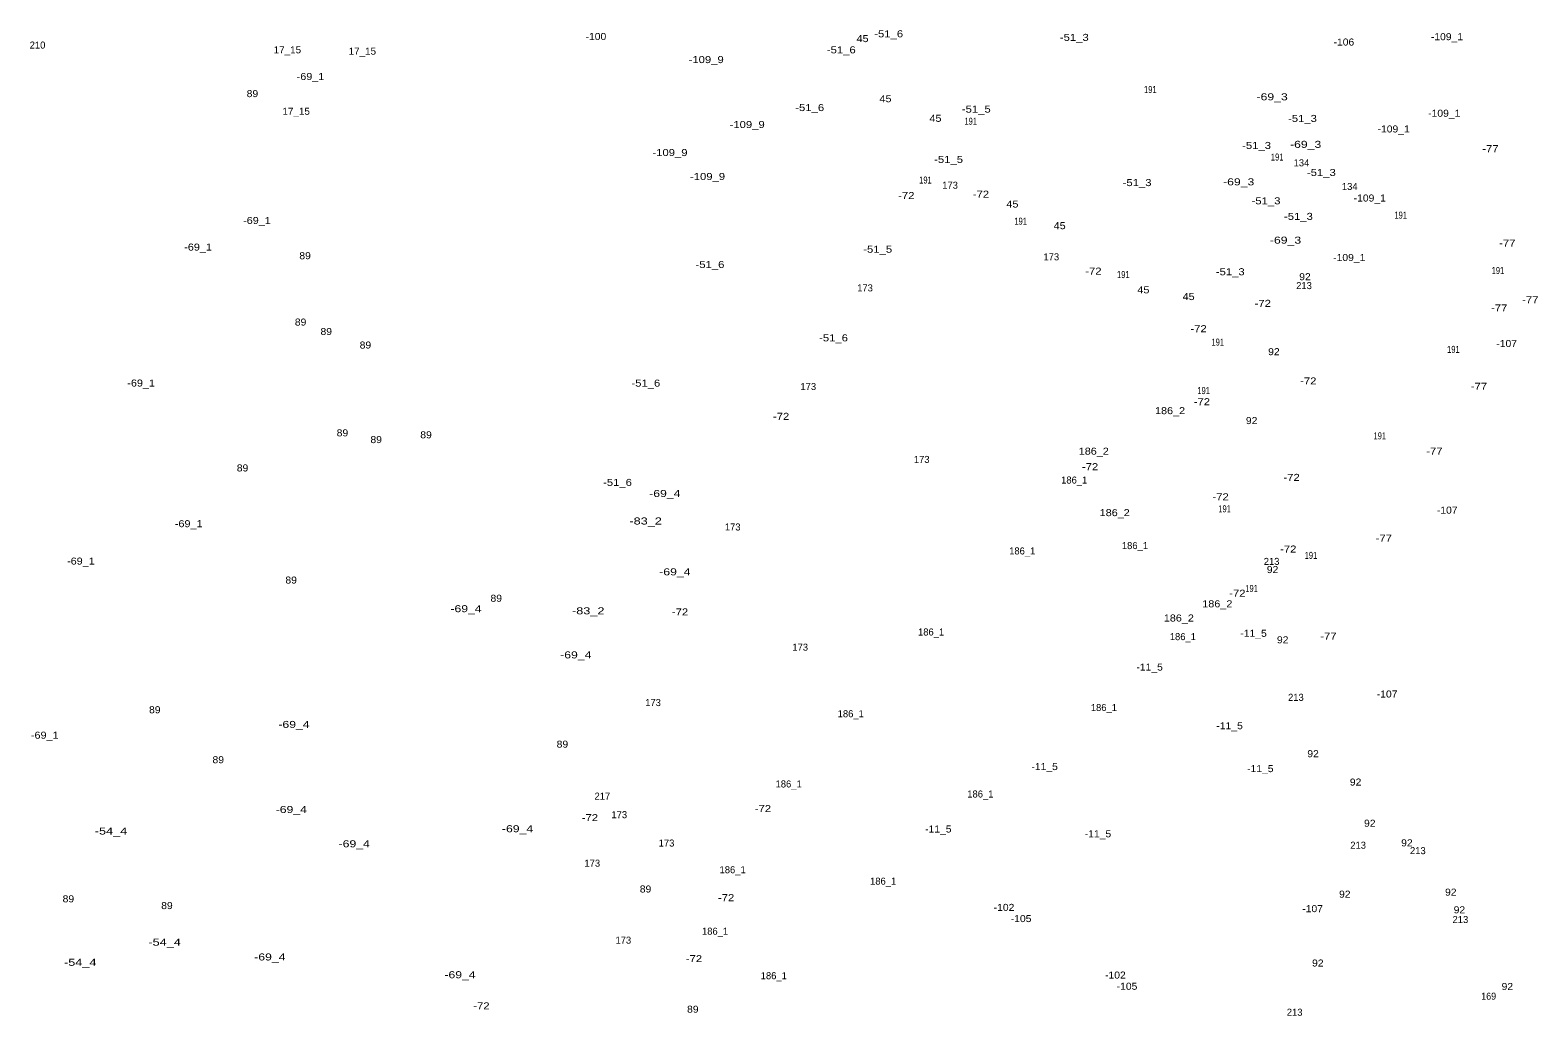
# Model space of a CAD drawing. Extents: x -662996 to -659766, y -998554 to -993949.
# Drawn here: x -660768 to -659910, y -996835 to -996274 of the extents above; entities that cross this region are included whole.
import ezdxf
from ezdxf.enums import TextEntityAlignment as Align

# ---------------------------------------------------------------- set-up
doc = ezdxf.new("R2010")
doc.units = 0
doc.header["$LTSCALE"] = 1.6
doc.layers.add('24', color=7, linetype='Continuous')

msp = doc.modelspace()

# ---------------------------------------------------------------- texts
at = {"layer": '24'}
for s, width, p in [('-100', 1.1, (-660445.981, -996279.57)), ('45', 1.15, (-660294.29, -996280.8)), ('-51_6', 1.2, (-660279.421, -996278.06)), ('-51_3', 1.2, (-660173.84, -996280.11)), ('-109_1', 1.1, (-659961.841, -996279.71)), ('17_15', 1.05, (-660621.48, -996287.18)), ('17_15', 1.05, (-660578.85, -996287.95)), ('-51_6', 1.2, (-660306.39, -996287.19)), ('-106', 1.1, (-660020.48, -996282.75)), ('-109_9', 1.2, (-660383.25, -996292.74)), ('-69_1', 1.15, (-660608.33, -996302.34)), ('89', 1.1, (-660641.37, -996312.09)), ('45', 1.15, (-660281.24, -996314.99)), ('191', 0.8, (-660130.62, -996309.76)), ('-69_3', 1.3, (-660061.29, -996313.9)), ('17_15', 1.05, (-660616.49, -996322.14)), ('-51_6', 1.2, (-660324.351, -996320.03)), ('-51_5', 1.2, (-660229.59, -996320.9)), ('-109_1', 1.1, (-659963.39, -996323.26)), ('-109_9', 1.2, (-660359.93, -996329.68)), ('45', 1.15, (-660252.819, -996326.13)), ('191', 0.8, (-660232.76, -996327.81)), ('-51_3', 1.2, (-660044.04, -996326.21)), ('-109_1', 1.1, (-659992.16, -996332.2)), ('-51_3', 1.2, (-660070.15, -996341.57)), ('-69_3', 1.3, (-660042.25, -996340.95)), ('-109_9', 1.2, (-660403.85, -996345.62)), ('-51_5', 1.2, (-660245.35, -996349.52)), ('191', 0.8, (-660058.421, -996348.17)), ('-77', 1.2, (-659937.12, -996343.41)), ('-51_3', 1.2, (-660033.29, -996356.94)), ('-109_9', 1.2, (-660382.47, -996359.23)), ('191', 0.8, (-660258.49, -996361.24)), ('-51_3', 1.2, (-660138.12, -996362.7)), ('-69_3', 1.3, (-660080.33, -996362.28)), ('-72', 1.2, (-660269.4, -996370.07)), ('-72', 1.2, (-660226.941, -996369.29)), ('45', 1.15, (-660209.04, -996374.91)), ('-51_3', 1.2, (-660064.78, -996373.07)), ('-109_1', 1.1, (-660005.76, -996371.47)), ('-69_1', 1.15, (-660638.79, -996384.24)), ('191', 0.8, (-660204.351, -996384.67)), ('-51_3', 1.2, (-660046.34, -996381.91)), ('191', 0.8, (-659988.15, -996381.21)), ('45', 1.15, (-660182.16, -996387.21)), ('-69_1', 1.15, (-660672.3, -996399.38)), ('-51_5', 1.2, (-660285.669, -996400.61)), ('-69_3', 1.3, (-660053.68, -996395.43)), ('-77', 1.2, (-659927.52, -996397.11)), ('89', 1.1, (-660611.42, -996404.29)), ('-51_6', 1.2, (-660381.091, -996409.3)), ('-109_1', 1.1, (-660017.421, -996405.3)), ('-72', 1.2, (-660162.961, -996413.05)), ('191', 0.8, (-660145.981, -996415.02)), ('-51_3', 1.2, (-660085.13, -996413.41)), ('92', 1.1, (-660042.61, -996416.24)), ('191', 0.8, (-659932.851, -996412.71)), ('45', 1.15, (-660134.54, -996423.7)), ('45', 1.15, (-660108.809, -996427.54)), ('-72', 1.2, (-660066.611, -996431.39)), ('-77', 1.2, (-659932.13, -996433.99)), ('-77', 1.2, (-659914.459, -996429.38)), ('89', 1.1, (-660613.96, -996442.03)), ('89', 1.1, (-660599.37, -996447.41)), ('-51_6', 1.2, (-660310.811, -996451.02)), ('-72', 1.2, (-660103.171, -996445.81)), ('191', 0.8, (-660092.211, -996453.43)), ('89', 1.1, (-660577.1, -996455.1)), ('92', 1.1, (-660060.28, -996458.88)), ('191', 0.8, (-659958.191, -996457.57)), ('-107', 1.1, (-659927.88, -996454.22)), ('-69_1', 1.15, (-660704.67, -996476.71)), ('-51_6', 1.2, (-660417.571, -996476.76)), ('-72', 1.2, (-660040.721, -996475.52)), ('-77', 1.2, (-659943.65, -996478.55)), ('-72', 1.2, (-660101.27, -996487.34)), ('191', 0.8, (-660100.28, -996481.01)), ('-72', 1.2, (-660340.62, -996495.66)), ('186_2', 1.15, (-660119.36, -996492.42)), ('92', 1.1, (-660072.95, -996498.07)), ('89', 1.1, (-660590.16, -996505.04)), ('89', 1.1, (-660570.96, -996508.88)), ('89', 1.1, (-660542.61, -996506.17)), ('191', 0.8, (-660000.051, -996506.74)), ('186_2', 1.15, (-660162.76, -996515.47)), ('-77', 1.2, (-659968.99, -996515.43)), ('89', 1.1, (-660646.99, -996525.01)), ('-72', 1.2, (-660164.861, -996524.29)), ('-72', 1.2, (-660050.24, -996530.38)), ('-51_6', 1.2, (-660433.701, -996533.23)), ('-69_4', 1.3, (-660406.77, -996539.54)), ('-72', 1.2, (-660090.611, -996541.43)), ('-83_2', 1.35, (-660417.699, -996555.18)), ('186_2', 1.15, (-660150.85, -996550.43)), ('191', 0.8, (-660088.37, -996548.23)), ('-107', 1.1, (-659961.7, -996548.99)), ('-69_1', 1.15, (-660677.63, -996556.71)), ('-72', 1.2, (-660052.14, -996571.14)), ('-77', 1.2, (-659997.79, -996564.99)), ('-69_1', 1.15, (-660738.95, -996577.97)), ('191', 0.8, (-660039.221, -996574.74)), ('89', 1.1, (-660619.34, -996588.78)), ('-69_4', 1.3, (-660401.051, -996584.11)), ('92', 1.1, (-660061.05, -996582.81)), ('89', 1.1, (-660502.67, -996599.13)), ('-72', 1.2, (-660081.081, -996596.28)), ('191', 0.8, (-660073.01, -996593.56)), ('-69_4', 1.3, (-660519.87, -996605.06)), ('-83_2', 1.35, (-660450.34, -996606.27)), ('-72', 1.2, (-660398.12, -996606.9)), ('186_2', 1.15, (-660092.48, -996602.29)), ('186_2', 1.15, (-660114.37, -996610.36)), ('-11_5', 1.1, (-660071.86, -996619.05)), ('92', 1.1, (-660055.29, -996622.76)), ('-77', 1.2, (-660029.28, -996620.69)), ('-69_4', 1.3, (-660457.41, -996631.35)), ('-11_5', 1.1, (-660131, -996638.26)), ('-107', 1.1, (-659995.9, -996653.59)), ('89', 1.1, (-660696.91, -996662.54)), ('-69_4', 1.3, (-660617.74, -996670.89)), ('-11_5', 1.1, (-660085.5, -996671.62)), ('-69_1', 1.15, (-660759.51, -996677.02)), ('89', 1.1, (-660465.04, -996682.11)), ('89', 1.1, (-660660.81, -996690.97)), ('92', 1.1, (-660038.01, -996687.53)), ('-11_5', 1.1, (-660190.72, -996694.86)), ('-11_5', 1.1, (-660068.02, -996696.02)), ('92', 1.1, (-660013.81, -996703.66)), ('-69_4', 1.3, (-660619.26, -996719.27)), ('-72', 1.2, (-660350.971, -996718.76)), ('-72', 1.2, (-660449.41, -996723.91)), ('92', 1.1, (-660005.75, -996727.09)), ('-54_4', 1.35, (-660721.81, -996731.53)), ('-69_4', 1.3, (-660490.541, -996730.21)), ('-11_5', 1.1, (-660251.199, -996730.38)), ('-11_5', 1.1, (-660160.38, -996733.09)), ('-69_4', 1.3, (-660583.461, -996738.78)), ('92', 1.1, (-659984.63, -996738.23)), ('89', 1.1, (-660746.07, -996770.1)), ('89', 1.1, (-660417.73, -996764.49)), ('-72', 1.2, (-660371.91, -996769.43)), ('92', 1.1, (-660019.96, -996767.43)), ('92', 1.1, (-659959.67, -996766.28)), ('89', 1.1, (-660690, -996773.94)), ('-102', 1.1, (-660213.821, -996774.95)), ('-107', 1.1, (-660038.27, -996775.68)), ('92', 1.1, (-659954.76, -996776.33)), ('-105', 1.1, (-660204.101, -996781.33)), ('-54_4', 1.35, (-660691.34, -996794.77)), ('-69_4', 1.3, (-660631.451, -996803.16)), ('-72', 1.2, (-660390.191, -996804.09)), ('-54_4', 1.35, (-660739.33, -996806.2)), ('-69_4', 1.3, (-660523.291, -996813.26)), ('-102', 1.1, (-660150.461, -996813.45)), ('92', 1.1, (-660035.32, -996806.61)), ('-105', 1.1, (-660143.861, -996819.82)), ('92', 1.1, (-659927.49, -996819.93)), ('169', 0.95, (-659938.12, -996825.47)), ('-72', 1.2, (-660511.101, -996830.96)), ('89', 1.1, (-660390.85, -996832.87))]:
    msp.add_text(s, height=4, dxfattribs=dict(at, width=width)).set_placement(p, align=Align.CENTER)
for s, p in [('210', (-660763.62, -996284.47)), ('134', (-660044.61, -996351.45)), ('173', (-660244.52, -996364.2)), ('134', (-660017.15, -996364.9)), ('173', (-660186.921, -996404.92)), ('173', (-660292.9, -996422.59)), ('213', (-660043.169, -996421.29)), ('173', (-660325.16, -996478.68)), ('173', (-660260.65, -996520.16)), ('186_1', (-660173.89, -996531.88)), ('173', (-660368.171, -996558.58)), ('186_1', (-660203.46, -996572.22)), ('186_1', (-660139.33, -996569.17)), ('213', (-660061.6, -996578.16)), ('186_1', (-660255.3, -996618.32)), ('186_1', (-660112.07, -996620.96)), ('173', (-660329.77, -996626.96)), ('173', (-660413.481, -996658.46)), ('213', (-660047.77, -996655.48)), ('186_1', (-660301, -996664.8)), ('186_1', (-660157, -996661.3)), ('186_1', (-660336.33, -996704.75)), ('186_1', (-660227.27, -996710.47)), ('217', (-660442.301, -996711.67)), ('173', (-660432.681, -996722.23)), ('173', (-660405.801, -996738.36)), ('213', (-660012.39, -996739.6)), ('213', (-659978.41, -996742.68)), ('173', (-660448.041, -996749.8)), ('186_1', (-660368.2, -996753.54)), ('186_1', (-660282.57, -996760.03)), ('213', (-659954.209, -996781.86)), ('173', (-660430.38, -996793.59)), ('186_1', (-660378.19, -996788.5)), ('186_1', (-660344.78, -996813.81)), ('213', (-660048.49, -996834.59))]:
    msp.add_text(s, height=4, dxfattribs=at).set_placement(p, align=Align.CENTER)

doc.saveas('drawing.dxf')
